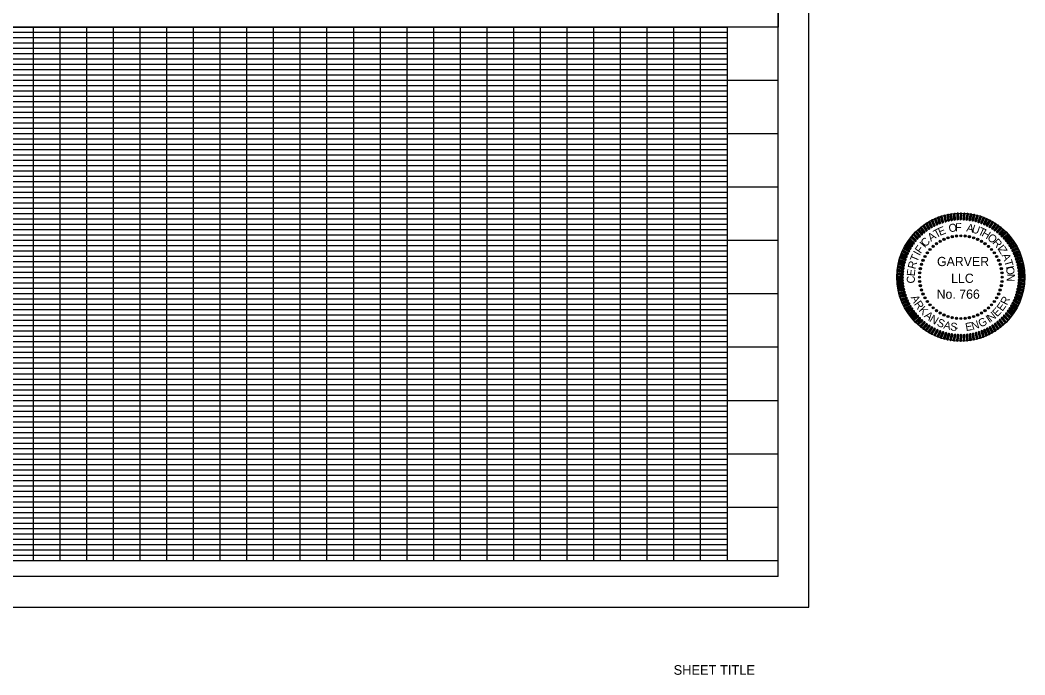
# Model space of a CAD drawing. Extents: x 0 to 19, y -0.6 to 11.2.
# Drawn here: x 9.61 to 19.02, y -0.63 to 5.5 of the extents above; entities that cross this region are included whole.
import ezdxf

# ---------------------------------------------------------------- set-up
doc = ezdxf.new("R2010")
doc.units = 0
for name, color, linetype in [('G-ANNO-STMP', 7, 'Continuous'), ('G-ANNO-TEXT', 7, 'Continuous'), ('G-Border-Paper', 7, 'Continuous'), ('G-Border-Sheet', 7, 'Continuous'), ('G-Grid-Border', 7, 'Continuous'), ('G-Grid-Major', 7, 'Continuous'), ('G-Grid-Minor', 7, 'Continuous'), ('G-No Plot-Border-1', 7, 'Continuous'), ('G-No Plot-Border-2', 7, 'Continuous'), ('G-No Plot-Stamp-1', 7, 'Continuous'), ('G-No Plot-Stamp-2', 7, 'Continuous')]:
    doc.layers.add(name, color=color, linetype=linetype)

# ---------------------------------------------------------------- blocks, each defined once
blk = doc.blocks.new('SEALDO')
at = {"layer": 'G-ANNO-TEXT'}
for radius in [0.0396, 0.0305, 0.0213, 0.0122, 0.00305]:
    blk.add_circle((1.403, -0.456), radius, dxfattribs=at)
blk = doc.blocks.new('SEALRI')
at = {"layer": 'G-ANNO-TEXT'}
for p, q in [((-0.023, 2.258), (-0.038, 2.081)), ((-0.008, 2.281), (-0.028, 2.056)), ((0.004, 2.286), (-0.016, 2.049)), ((0.016, 2.285), (-0.004, 2.048)), ((0.028, 2.278), (0.008, 2.052)), ((0.023, 2.076), (0.038, 2.253))]:
    blk.add_line(p, q, dxfattribs=at)
for centre, start, end in [((0.008, 2.256), 355, 175), ((-0.008, 2.078), 175, 355)]:
    blk.add_arc(centre, 0.0305, start, end, dxfattribs=at)

msp = doc.modelspace()

# ---------------------------------------------------------------- linework, layer by layer
at = {"layer": 'G-Border-Paper'}
msp.add_lwpolyline([(17, 11), (0, 11), (0, 0), (17, 0)], close=True, dxfattribs=at)
at = {"layer": 'G-Border-Sheet'}
for q in [(16.7116, 10.7116), (0.758, 0.2884)]:
    msp.add_line((16.7116, 0.2884), q, dxfattribs=at)
at = {"layer": 'G-Grid-Border'}
for p, q in [((16.7116, 5.4354), (0.758, 5.4354)), ((16.7116, 0.4354), (0.758, 0.4354))]:
    msp.add_line(p, q, dxfattribs=at)
msp.add_lwpolyline([(1.2348, 5.4354), (16.2348, 5.4354), (16.2348, 0.4354), (1.2348, 0.4354)], close=True, dxfattribs=at)
at = {"layer": 'G-Grid-Major'}
for p, q in [((9.7348, 0.4354), (9.7348, 5.4354)), ((10.2348, 0.4354), (10.2348, 5.4354)), ((10.7348, 0.4354), (10.7348, 5.4354)), ((11.2348, 0.4354), (11.2348, 5.4354)), ((11.7348, 0.4354), (11.7348, 5.4354)), ((12.2348, 0.4354), (12.2348, 5.4354)), ((12.7348, 0.4354), (12.7348, 5.4354)), ((13.2348, 0.4354), (13.2348, 5.4354)), ((13.7348, 0.4354), (13.7348, 5.4354)), ((14.2348, 0.4354), (14.2348, 5.4354)), ((14.7348, 0.4354), (14.7348, 5.4354)), ((15.2348, 0.4354), (15.2348, 5.4354)), ((15.7348, 0.4354), (15.7348, 5.4354)), ((16.7116, 4.9354), (0.758, 4.9354)), ((16.7116, 4.4354), (0.758, 4.4354)), ((16.7116, 3.9354), (0.758, 3.9354)), ((16.7116, 3.4354), (0.758, 3.4354)), ((16.7116, 2.9354), (0.758, 2.9354)), ((16.7116, 2.4354), (0.758, 2.4354)), ((16.7116, 1.9354), (0.758, 1.9354)), ((16.7116, 1.4354), (0.758, 1.4354)), ((16.7116, 0.9354), (0.758, 0.9354))]:
    msp.add_line(p, q, dxfattribs=at)
msp.add_lwpolyline([(1.2348, 5.4354), (16.2348, 5.4354), (16.2348, 0.4354), (1.2348, 0.4354)], close=True, dxfattribs=at)
at = {"layer": 'G-Grid-Minor'}
for p, q in [((16.2348, 5.3854), (1.2348, 5.3854)), ((9.9848, 0.4354), (9.9848, 5.4354)), ((10.4848, 0.4354), (10.4848, 5.4354)), ((10.9848, 0.4354), (10.9848, 5.4354)), ((11.4848, 0.4354), (11.4848, 5.4354)), ((11.9848, 0.4354), (11.9848, 5.4354)), ((12.4848, 0.4354), (12.4848, 5.4354)), ((12.9848, 0.4354), (12.9848, 5.4354)), ((13.4848, 0.4354), (13.4848, 5.4354)), ((13.9848, 0.4354), (13.9848, 5.4354)), ((14.4848, 0.4354), (14.4848, 5.4354)), ((14.9848, 0.4354), (14.9848, 5.4354)), ((15.4848, 0.4354), (15.4848, 5.4354)), ((15.9848, 0.4354), (15.9848, 5.4354)), ((16.2348, 5.3354), (1.2348, 5.3354)), ((16.2348, 5.2854), (1.2348, 5.2854)), ((16.2348, 5.2354), (1.2348, 5.2354)), ((16.2348, 5.1854), (1.2348, 5.1854)), ((16.2348, 5.1354), (1.2348, 5.1354)), ((16.2348, 5.0854), (1.2348, 5.0854)), ((16.2348, 5.0354), (1.2348, 5.0354)), ((16.2348, 4.9854), (1.2348, 4.9854)), ((16.2348, 4.8854), (1.2348, 4.8854)), ((16.2348, 4.8354), (1.2348, 4.8354)), ((16.2348, 4.7854), (1.2348, 4.7854)), ((16.2348, 4.7354), (1.2348, 4.7354)), ((16.2348, 4.6854), (1.2348, 4.6854)), ((16.2348, 4.6354), (1.2348, 4.6354)), ((16.2348, 4.5854), (1.2348, 4.5854)), ((16.2348, 4.5354), (1.2348, 4.5354)), ((16.2348, 4.4854), (1.2348, 4.4854)), ((16.2348, 4.3854), (1.2348, 4.3854)), ((16.2348, 4.3354), (1.2348, 4.3354)), ((16.2348, 4.2854), (1.2348, 4.2854)), ((16.2348, 4.2354), (1.2348, 4.2354)), ((16.2348, 4.1854), (1.2348, 4.1854)), ((16.2348, 4.1354), (1.2348, 4.1354)), ((16.2348, 4.0854), (1.2348, 4.0854)), ((16.2348, 4.0354), (1.2348, 4.0354)), ((16.2348, 3.9854), (1.2348, 3.9854)), ((16.2348, 3.8854), (1.2348, 3.8854)), ((16.2348, 3.8354), (1.2348, 3.8354)), ((16.2348, 3.7854), (1.2348, 3.7854)), ((16.2348, 3.7354), (1.2348, 3.7354)), ((16.2348, 3.6854), (1.2348, 3.6854)), ((16.2348, 3.6354), (1.2348, 3.6354)), ((16.2348, 3.5854), (1.2348, 3.5854)), ((16.2348, 3.5354), (1.2348, 3.5354)), ((16.2348, 3.4854), (1.2348, 3.4854)), ((16.2348, 3.3854), (1.2348, 3.3854)), ((16.2348, 3.3354), (1.2348, 3.3354)), ((16.2348, 3.2854), (1.2348, 3.2854)), ((16.2348, 3.2354), (1.2348, 3.2354)), ((16.2348, 3.1854), (1.2348, 3.1854)), ((16.2348, 3.1354), (1.2348, 3.1354)), ((16.2348, 3.0854), (1.2348, 3.0854)), ((16.2348, 3.0354), (1.2348, 3.0354)), ((16.2348, 2.9854), (1.2348, 2.9854)), ((16.2348, 2.8854), (1.2348, 2.8854)), ((16.2348, 2.8354), (1.2348, 2.8354)), ((16.2348, 2.7854), (1.2348, 2.7854)), ((16.2348, 2.7354), (1.2348, 2.7354)), ((16.2348, 2.6854), (1.2348, 2.6854)), ((16.2348, 2.6354), (1.2348, 2.6354)), ((16.2348, 2.5854), (1.2348, 2.5854)), ((16.2348, 2.5354), (1.2348, 2.5354)), ((16.2348, 2.4854), (1.2348, 2.4854)), ((16.2348, 2.3854), (1.2348, 2.3854)), ((16.2348, 2.3354), (1.2348, 2.3354)), ((16.2348, 2.2854), (1.2348, 2.2854)), ((16.2348, 2.2354), (1.2348, 2.2354)), ((16.2348, 2.1854), (1.2348, 2.1854)), ((16.2348, 2.1354), (1.2348, 2.1354)), ((16.2348, 2.0854), (1.2348, 2.0854)), ((16.2348, 2.0354), (1.2348, 2.0354)), ((16.2348, 1.9854), (1.2348, 1.9854)), ((16.2348, 1.8854), (1.2348, 1.8854)), ((16.2348, 1.8354), (1.2348, 1.8354)), ((16.2348, 1.7854), (1.2348, 1.7854)), ((16.2348, 1.7354), (1.2348, 1.7354)), ((16.2348, 1.6854), (1.2348, 1.6854)), ((16.2348, 1.6354), (1.2348, 1.6354)), ((16.2348, 1.5854), (1.2348, 1.5854)), ((16.2348, 1.5354), (1.2348, 1.5354)), ((16.2348, 1.4854), (1.2348, 1.4854)), ((16.2348, 1.3854), (1.2348, 1.3854)), ((16.2348, 1.3354), (1.2348, 1.3354)), ((16.2348, 1.2854), (1.2348, 1.2854)), ((16.2348, 1.2354), (1.2348, 1.2354)), ((16.2348, 1.1854), (1.2348, 1.1854)), ((16.2348, 1.1354), (1.2348, 1.1354)), ((16.2348, 1.0854), (1.2348, 1.0854)), ((16.2348, 1.0354), (1.2348, 1.0354)), ((16.2348, 0.9854), (1.2348, 0.9854)), ((16.2348, 0.8854), (1.2348, 0.8854)), ((16.2348, 0.8354), (1.2348, 0.8354)), ((16.2348, 0.7854), (1.2348, 0.7854)), ((16.2348, 0.7354), (1.2348, 0.7354)), ((16.2348, 0.6854), (1.2348, 0.6854)), ((16.2348, 0.6354), (1.2348, 0.6354)), ((16.2348, 0.5854), (1.2348, 0.5854)), ((16.2348, 0.5354), (1.2348, 0.5354)), ((16.2348, 0.4854), (1.2348, 0.4854))]:
    msp.add_line(p, q, dxfattribs=at)
at = {"layer": 'G-No Plot-Border-1'}
msp.add_lwpolyline([(0.758, 5.4354), (0.758, 10.7116), (13.7281, 10.7116), (13.7281, 10.2161), (14.7206, 10.2161), (14.8974, 10.2161), (15.4366, 10.2161), (15.4366, 8.7411), (16.7116, 8.7411), (16.7116, 5.4354)], close=True, dxfattribs=at)
at = {"layer": 'G-No Plot-Border-2'}
msp.add_lwpolyline([(0.758, 5.4354), (0.758, 10.7116), (12.3781, 10.7116), (12.3781, 9.2366), (13.7281, 9.2366), (13.7281, 10.2161), (14.7206, 10.2161), (14.8974, 10.2161), (16.7116, 10.2161), (16.7116, 5.4354)], close=True, dxfattribs=at)
at = {"layer": 'G-No Plot-Stamp-1'}
msp.add_circle((18.4222, 3.0925), 0.6, dxfattribs=at)
at = {"layer": 'G-No Plot-Stamp-2'}
msp.add_circle((18.4222, 3.0925), 0.6, dxfattribs=at)

# ---------------------------------------------------------------- block references
at = {"layer": 'G-ANNO-STMP'}
for name, xscale, yscale, rotation in [('SEALRI', 0.2624620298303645, 0.2624620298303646, 15.000000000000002), ('SEALRI', 0.2624620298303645, 0.2624620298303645, 12.000000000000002), ('SEALRI', 0.2624620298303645, 0.2624620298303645, 9), ('SEALRI', 0.2624620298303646, 0.26246202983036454, 6), ('SEALRI', 0.2624620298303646, 0.2624620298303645, 3.0000000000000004), ('SEALRI', 0.26246202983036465, 0.2624620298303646, -2.9999999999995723), ('SEALRI', 0.2624620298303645, 0.2624620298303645, -5.9999999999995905), ('SEALRI', 0.2624620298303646, 0.26246202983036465, -8.999999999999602), ('SEALRI', 0.2624620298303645, 0.26246202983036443, -11.999999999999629), ('SEALRI', 0.2624620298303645, 0.2624620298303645, -14.999999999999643), ('SEALRI', 0.2624620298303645, 0.2624620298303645, 36), ('SEALRI', 0.2624620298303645, 0.26246202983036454, 33), ('SEALRI', 0.2624620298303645, 0.2624620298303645, 30.00000000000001), ('SEALRI', 0.2624620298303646, 0.26246202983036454, 26.99999999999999), ('SEALRI', 0.26246202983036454, 0.26246202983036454, 23.99999999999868), ('SEALRI', 0.26246202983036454, 0.26246202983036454, 20.999999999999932), ('SEALRI', 0.2624620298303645, 0.26246202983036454, 18), ('SEALRI', 0.26246202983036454, 0.2624620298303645, -17.99999999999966), ('SEALRI', 0.2624620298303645, 0.26246202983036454, -20.999999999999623), ('SEALRI', 0.2624620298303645, 0.26246202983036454, -23.999999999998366), ('SEALRI', 0.26246202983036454, 0.26246202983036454, -26.999999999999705), ('SEALRI', 0.26246202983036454, 0.2624620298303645, -29.99999999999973), ('SEALRI', 0.26246202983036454, 0.2624620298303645, -32.999999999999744), ('SEALRI', 0.2624620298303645, 0.2624620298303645, -35.999999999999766), ('SEALRI', 0.2624620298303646, 0.26246202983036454, 47.99999999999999), ('SEALRI', 0.26246202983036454, 0.2624620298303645, 44.999999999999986), ('SEALRI', 0.26246202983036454, 0.2624620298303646, 41.999999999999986), ('SEALRI', 0.26246202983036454, 0.26246202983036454, 38.999999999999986), ('SEALDO', 0.2624620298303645, 0.26246202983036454, 119.99999999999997), ('SEALDO', 0.2624620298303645, 0.26246202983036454, 113.99999999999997), ('SEALDO', 0.26246202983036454, 0.2624620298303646, 107.99999999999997), ('SEALDO', 0.26246202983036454, 0.26246202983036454, 101.99999999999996), ('SEALRI', 0.26246202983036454, 0.2624620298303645, -38.999999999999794), ('SEALRI', 0.26246202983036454, 0.2624620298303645, -41.99999999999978), ('SEALRI', 0.26246202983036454, 0.2624620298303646, -44.999999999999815), ('SEALRI', 0.26246202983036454, 0.2624620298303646, -47.99999999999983), ('SEALRI', 0.2624620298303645, 0.2624620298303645, 59.999999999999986), ('SEALRI', 0.26246202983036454, 0.2624620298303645, 56.99999999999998), ('SEALRI', 0.2624620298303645, 0.2624620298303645, 54), ('SEALRI', 0.26246202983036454, 0.26246202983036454, 50.99999999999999), ('SEALDO', 0.26246202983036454, 0.2624620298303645, 150), ('SEALDO', 0.2624620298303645, 0.26246202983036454, 144), ('SEALDO', 0.26246202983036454, 0.26246202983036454, 138), ('SEALDO', 0.2624620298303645, 0.26246202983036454, 131.99999999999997), ('SEALDO', 0.2624620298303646, 0.26246202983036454, 125.99999999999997), ('SEALDO', 0.2624620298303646, 0.2624620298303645, 95.99999999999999), ('SEALDO', 0.26246202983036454, 0.26246202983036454, 90), ('SEALDO', 0.2624620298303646, 0.26246202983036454, 83.99999999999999), ('SEALDO', 0.2624620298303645, 0.26246202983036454, 77.99999999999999), ('SEALDO', 0.2624620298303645, 0.26246202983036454, 72), ('SEALDO', 0.26246202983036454, 0.2624620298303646, 66.00000000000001), ('SEALRI', 0.2624620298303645, 0.26246202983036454, -50.999999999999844), ('SEALRI', 0.2624620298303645, 0.26246202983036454, -53.99999999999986), ('SEALRI', 0.2624620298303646, 0.26246202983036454, -56.999999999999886), ('SEALRI', 0.2624620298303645, 0.26246202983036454, -59.99999999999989), ('SEALRI', 0.26246202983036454, 0.2624620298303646, 68.99999999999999), ('SEALRI', 0.26246202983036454, 0.2624620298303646, 65.99999999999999), ('SEALRI', 0.26246202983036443, 0.2624620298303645, 63), ('SEALDO', 0.26246202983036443, 0.2624620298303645, 168.00000000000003), ('SEALDO', 0.2624620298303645, 0.26246202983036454, 162.00000000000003), ('SEALDO', 0.26246202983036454, 0.2624620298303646, 156.00000000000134), ('SEALDO', 0.26246202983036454, 0.2624620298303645, 60.00000000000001), ('SEALDO', 0.2624620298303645, 0.2624620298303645, 54), ('SEALDO', 0.26246202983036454, 0.2624620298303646, 48.00000000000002), ('SEALRI', 0.2624620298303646, 0.26246202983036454, -62.99999999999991), ('SEALRI', 0.26246202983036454, 0.2624620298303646, -65.99999999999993), ('SEALRI', 0.26246202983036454, 0.26246202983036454, -68.99999999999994), ('SEALRI', 0.2624620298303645, 0.2624620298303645, 78.00000000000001), ('SEALRI', 0.2624620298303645, 0.26246202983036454, 75.00000000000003), ('SEALRI', 0.2624620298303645, 0.26246202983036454, 72), ('SEALDO', 0.26246202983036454, 0.26246202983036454, -179.99999999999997), ('SEALDO', 0.2624620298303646, 0.2624620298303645, 174.00000000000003), ('SEALDO', 0.2624620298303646, 0.26246202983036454, 42.000000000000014), ('SEALDO', 0.2624620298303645, 0.2624620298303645, 36), ('SEALRI', 0.26246202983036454, 0.26246202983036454, -71.99999999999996), ('SEALRI', 0.26246202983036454, 0.2624620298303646, -74.99999999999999), ('SEALRI', 0.2624620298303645, 0.2624620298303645, -78), ('SEALRI', 0.26246202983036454, 0.26246202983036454, 87.00000000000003), ('SEALRI', 0.2624620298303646, 0.26246202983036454, 84.00000000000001), ('SEALRI', 0.2624620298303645, 0.2624620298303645, 81), ('SEALDO', 0.2624620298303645, 0.26246202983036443, -167.99999999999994), ('SEALDO', 0.26246202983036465, 0.26246202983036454, -173.99999999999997), ('SEALDO', 0.26246202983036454, 0.2624620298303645, 29.999999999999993), ('SEALDO', 0.26246202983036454, 0.26246202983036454, 23.99999999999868), ('SEALRI', 0.2624620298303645, 0.2624620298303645, -81.00000000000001), ('SEALRI', 0.2624620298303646, 0.2624620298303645, -84.00000000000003), ('SEALRI', 0.26246202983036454, 0.26246202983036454, -87.00000000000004), ('SEALRI', 0.26246202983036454, 0.26246202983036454, 90.00000000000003), ('SEALRI', 0.2624620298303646, 0.2624620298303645, 93), ('SEALRI', 0.2624620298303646, 0.26246202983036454, 96.00000000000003), ('SEALRI', 0.26246202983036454, 0.26246202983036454, 99.00000000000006), ('SEALDO', 0.2624620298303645, 0.26246202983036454, -161.99999999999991), ('SEALDO', 0.2624620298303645, 0.26246202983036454, -156.00000000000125), ('SEALDO', 0.26246202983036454, 0.26246202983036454, -149.99999999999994), ('SEALDO', 0.2624620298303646, 0.26246202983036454, 6), ('SEALDO', 0.2624620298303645, 0.2624620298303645, 12.000000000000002), ('SEALDO', 0.2624620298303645, 0.26246202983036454, 18), ('SEALRI', 0.26246202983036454, 0.2624620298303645, -99.00000000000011), ('SEALRI', 0.26246202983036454, 0.2624620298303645, -96.0000000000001), ('SEALRI', 0.2624620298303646, 0.26246202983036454, -93.00000000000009), ('SEALRI', 0.26246202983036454, 0.26246202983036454, -90.00000000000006), ('SEALRI', 0.2624620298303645, 0.2624620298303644, 102.00000000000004), ('SEALRI', 0.26246202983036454, 0.2624620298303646, 105.00000000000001), ('SEALRI', 0.26246202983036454, 0.26246202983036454, 108.00000000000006), ('SEALDO', 0.2624620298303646, 0.26246202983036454, -143.99999999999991), ('SEALDO', 0.26246202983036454, 0.2624620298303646, -137.9999999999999), ('SEALDO', 0.26246202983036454, 0.2624620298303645, -6.000000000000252), ('SEALRI', 0.26246202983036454, 0.2624620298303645, -108.00000000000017), ('SEALRI', 0.26246202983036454, 0.2624620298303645, -105.00000000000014), ('SEALRI', 0.2624620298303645, 0.2624620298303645, -102.00000000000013), ('SEALRI', 0.2624620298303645, 0.2624620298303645, 111.00000000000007), ('SEALRI', 0.26246202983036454, 0.26246202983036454, 114.00000000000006), ('SEALRI', 0.26246202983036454, 0.26246202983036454, 117.00000000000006), ('SEALRI', 0.2624620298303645, 0.2624620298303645, 120.00000000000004), ('SEALDO', 0.26246202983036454, 0.26246202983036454, -131.99999999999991), ('SEALDO', 0.26246202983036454, 0.2624620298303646, -125.9999999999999), ('SEALDO', 0.2624620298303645, 0.26246202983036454, -119.99999999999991), ('SEALDO', 0.26246202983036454, 0.2624620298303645, -23.999999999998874), ('SEALDO', 0.2624620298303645, 0.26246202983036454, -18.000000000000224), ('SEALDO', 0.2624620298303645, 0.26246202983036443, -12.000000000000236), ('SEALRI', 0.26246202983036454, 0.2624620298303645, -120.00000000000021), ('SEALRI', 0.26246202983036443, 0.2624620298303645, -117.00000000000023), ('SEALRI', 0.26246202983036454, 0.2624620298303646, -114.0000000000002), ('SEALRI', 0.26246202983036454, 0.26246202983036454, -111.00000000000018), ('SEALRI', 0.2624620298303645, 0.2624620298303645, 123.00000000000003), ('SEALRI', 0.26246202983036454, 0.26246202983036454, 126.00000000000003), ('SEALRI', 0.26246202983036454, 0.26246202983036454, 129.00000000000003), ('SEALRI', 0.26246202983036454, 0.2624620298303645, 132), ('SEALDO', 0.26246202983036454, 0.26246202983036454, -113.99999999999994), ('SEALDO', 0.26246202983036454, 0.26246202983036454, -107.99999999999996), ('SEALDO', 0.2624620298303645, 0.26246202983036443, -101.99999999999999), ('SEALDO', 0.2624620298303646, 0.26246202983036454, -96), ('SEALDO', 0.26246202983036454, 0.26246202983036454, -90.00000000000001), ('SEALDO', 0.26246202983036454, 0.26246202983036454, -54.000000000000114), ('SEALDO', 0.26246202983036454, 0.26246202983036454, -48.00000000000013), ('SEALDO', 0.2624620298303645, 0.2624620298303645, -42.00000000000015), ('SEALDO', 0.2624620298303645, 0.2624620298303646, -36.00000000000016), ('SEALDO', 0.2624620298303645, 0.26246202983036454, -30.00000000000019), ('SEALRI', 0.2624620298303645, 0.26246202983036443, -132.00000000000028), ('SEALRI', 0.2624620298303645, 0.26246202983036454, -129.00000000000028), ('SEALRI', 0.26246202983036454, 0.2624620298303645, -126.00000000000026), ('SEALRI', 0.2624620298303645, 0.26246202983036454, -123.00000000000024), ('SEALRI', 0.2624620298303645, 0.26246202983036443, 135), ('SEALRI', 0.26246202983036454, 0.26246202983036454, 138), ('SEALRI', 0.2624620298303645, 0.26246202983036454, 140.99999999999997), ('SEALRI', 0.2624620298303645, 0.26246202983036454, 144), ('SEALRI', 0.2624620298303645, 0.26246202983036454, 146.99999999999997), ('SEALDO', 0.2624620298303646, 0.2624620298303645, -84.00000000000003), ('SEALDO', 0.26246202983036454, 0.26246202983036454, -78.00000000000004), ('SEALDO', 0.26246202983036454, 0.2624620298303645, -72.00000000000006), ('SEALDO', 0.2624620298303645, 0.26246202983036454, -66.00000000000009), ('SEALDO', 0.26246202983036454, 0.26246202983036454, -60.0000000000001), ('SEALRI', 0.26246202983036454, 0.2624620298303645, -147.00000000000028), ('SEALRI', 0.2624620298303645, 0.26246202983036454, -144.00000000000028), ('SEALRI', 0.26246202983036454, 0.2624620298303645, -141.0000000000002), ('SEALRI', 0.26246202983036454, 0.2624620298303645, -138.00000000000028), ('SEALRI', 0.2624620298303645, 0.2624620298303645, -135.00000000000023), ('SEALRI', 0.2624620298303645, 0.26246202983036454, 149.99999999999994), ('SEALRI', 0.2624620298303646, 0.26246202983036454, 152.99999999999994), ('SEALRI', 0.2624620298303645, 0.2624620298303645, 156.00000000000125), ('SEALRI', 0.2624620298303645, 0.26246202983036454, 159), ('SEALRI', 0.2624620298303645, 0.2624620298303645, 161.99999999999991), ('SEALRI', 0.2624620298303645, 0.26246202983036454, 164.99999999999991), ('SEALRI', 0.2624620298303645, 0.26246202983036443, 167.99999999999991), ('SEALRI', 0.26246202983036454, 0.2624620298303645, 170.9999999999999), ('SEALRI', 0.26246202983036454, 0.2624620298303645, 173.9999999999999), ('SEALRI', 0.2624620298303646, 0.2624620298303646, 176.9999999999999), ('SEALRI', 0.26246202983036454, 0.26246202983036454, 179.99999999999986), ('SEALRI', 0.2624620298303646, 0.26246202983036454, -177.00000000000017), ('SEALRI', 0.2624620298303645, 0.2624620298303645, -174.00000000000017), ('SEALRI', 0.26246202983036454, 0.2624620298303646, -171.00000000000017), ('SEALRI', 0.2624620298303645, 0.2624620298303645, -168.0000000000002), ('SEALRI', 0.2624620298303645, 0.2624620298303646, -165.0000000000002), ('SEALRI', 0.2624620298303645, 0.26246202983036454, -162.00000000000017), ('SEALRI', 0.26246202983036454, 0.26246202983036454, -159.00000000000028), ('SEALRI', 0.2624620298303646, 0.2624620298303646, -156.00000000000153), ('SEALRI', 0.2624620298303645, 0.2624620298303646, -153.00000000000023), ('SEALRI', 0.2624620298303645, 0.26246202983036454, -150.00000000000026)]:
    msp.add_blockref(name, (18.4223, 3.0925), dxfattribs=dict(at, xscale=xscale, yscale=yscale, rotation=rotation))
at = {"layer": 'G-ANNO-STMP', "xscale": 0.26246202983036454, "yscale": 0.26246202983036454}
for name in ['SEALRI', 'SEALDO']:
    msp.add_blockref(name, (18.4223, 3.0925), dxfattribs=at)

# ---------------------------------------------------------------- texts
at = {"layer": 'G-ANNO-STMP'}
for s, rotation, p in [('O', 8.2771, (18.3136, 3.5123)), ('F', 1.61044, (18.3705, 3.522)), ('A', 348.2771, (18.4707, 3.5227)), ('U', 341.27715, (18.5176, 3.5152)), ('A', 34.94377, (18.1428, 3.4228)), ('T', 28.2771, (18.1905, 3.4573)), ('E', 21.61044, (18.2267, 3.4785)), ('T', 334.94377, (18.5765, 3.4962)), ('H', 328.2771, (18.6103, 3.4828)), ('O', 319.7874, (18.6645, 3.452)), ('F', 54.94377, (18.0468, 3.3073)), ('I', 49.74076, (18.0858, 3.3622)), ('C', 44.38813, (18.0896, 3.3699)), ('R', 311.99331, (18.7137, 3.4128)), ('I', 307.00814, (18.7595, 3.3613)), ('T', 67.43139, (18.0126, 3.2289)), ('I', 61.61044, (18.0378, 3.2871)), ('Z', 301.61044, (18.7683, 3.3523)), ('A', 292.97516, (18.8037, 3.2978)), ('R', 74.94377, (17.9951, 3.1629)), ('T', 286.3085, (18.8272, 3.2435)), ('E', 83.89849, (17.9897, 3.0987)), ('I', 281.61044, (18.8422, 3.1908)), ('O', 276.48226, (18.8451, 3.1881)), ('N', 268.2771, (18.8545, 3.1248)), ('C', 91.88416, (17.993, 3.0347)), ('A', 296.57465, (17.9514, 2.9025)), ('R', 304.61826, (17.981, 2.8408)), ('E', 54.73091, (18.8126, 2.7672)), ('R', 63.09594, (18.8543, 2.8247)), ('K', 313.3805, (18.0231, 2.778)), ('A', 321.25836, (18.0738, 2.7232)), ('N', 329.10994, (18.1231, 2.6817)), ('I', 32.97899, (18.6876, 2.6612)), ('N', 38.98211, (18.705, 2.6701)), ('E', 46.68075, (18.7629, 2.7159)), ('S', 337.62936, (18.1923, 2.6396)), ('A', 345.40726, (18.2555, 2.613)), ('S', 352.80457, (18.3191, 2.5952)), ('E', 10.06947, (18.4713, 2.5871)), ('N', 17.86862, (18.5341, 2.5965)), ('G', 26.41319, (18.608, 2.6194)), ('-', 0.83848, (18.3644, 2.5854))]:
    msp.add_text(s, height=0.075, rotation=rotation, dxfattribs=at).set_placement(p)
for s, p in [('GARVER', (18.1993, 3.1961)), ('LLC', (18.3314, 3.039)), ('No. 766', (18.1956, 2.8903))]:
    msp.add_text(s, height=0.0864, dxfattribs=at).set_placement(p)
at = {"layer": 'G-ANNO-TEXT'}
msp.add_text('SHEET TITLE', height=0.09, dxfattribs=at).set_placement((15.7319, -0.6318))

doc.saveas('drawing.dxf')
